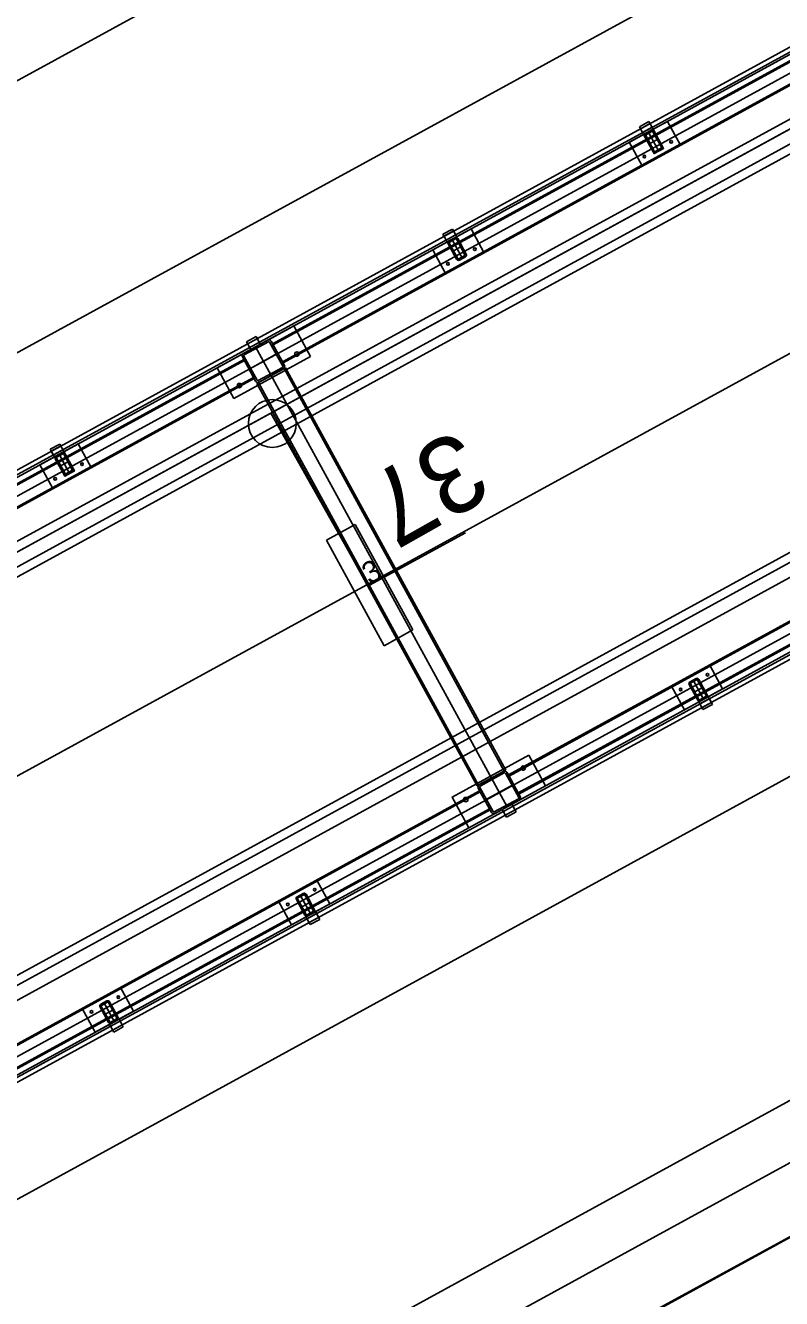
# Model space of a CAD drawing. Extents: x -783978 to -783565, y -1064821 to -1064596.
# Drawn here: x -783759.75 to -783756.29, y -1064681.64 to -1064675.81 of the extents above; entities that cross this region are included whole.
import ezdxf

# ---------------------------------------------------------------- set-up
doc = ezdxf.new("R2010")
doc.units = 0
for name, color, linetype in [('Default', 7, 'Continuous'), ('SO 01_11_01', 7, 'Continuous'), ('SO 01_20_01', 7, 'Continuous'), ('SO 01_50_01', 7, 'Continuous'), ('SO 01_74_01', 7, 'Continuous'), ('SO 01_86_02', 7, 'Continuous'), ('SO 01_86_03', 7, 'Continuous'), ('SO 01_86_04', 7, 'Continuous')]:
    doc.layers.add(name, color=color, linetype=linetype)

# ---------------------------------------------------------------- blocks, each defined once
blk = doc.blocks.new('POINT_DISPLAY')
at = {"layer": 'Default'}
blk.add_line((0, 0), (0, 0), dxfattribs=at)

msp = doc.modelspace()

# ---------------------------------------------------------------- linework, layer by layer
at = {"layer": 'SO 01_11_01'}
msp.add_line((-783772.8819, -1064683.2217), (-783730.898, -1064660.279), dxfattribs=at)
at = {"layer": 'SO 01_20_01'}
for p, q in [((-783735.0054, -1064663.7532), (-783787.4671, -1064692.4555)), ((-783735.2041, -1064664.4318), (-783786.7885, -1064692.6541)), ((-783786.6445, -1064692.9173), (-783735.3233, -1064664.839)), ((-783738.0171, -1064666.3812), (-783786.4402, -1064692.874)), ((-783786.421, -1064692.9091), (-783737.9979, -1064666.4163)), ((-783737.8741, -1064667.2605), (-783785.3352, -1064693.2269)), ((-783785.6531, -1064694.3127), (-783737.23, -1064667.82)), ((-783737.0912, -1064667.858), (-783785.7805, -1064694.4964)), ((-783737.2108, -1064667.855), (-783785.6339, -1064694.3478)), ((-783785.6366, -1064694.7596), (-783736.9472, -1064668.1212)), ((-783746.2961, -1064673.8055), (-783785.8354, -1064695.4379))]:
    msp.add_line(p, q, dxfattribs=at)
at = {"layer": 'SO 01_50_01'}
for p, q in [((-783786.7885, -1064692.6541), (-783725.4827, -1064659.1131)), ((-783760.47, -1064678.255), (-783756.0835, -1064675.8552)), ((-783760.4699, -1064678.2551), (-783756.0835, -1064675.8552)), ((-783760.4699, -1064678.2551), (-783756.0835, -1064675.8552))]:
    msp.add_line(p, q, dxfattribs=at)
for points in [[(-783784.7751, -1064696.3401), (-783745.2333, -1064674.7064)], [(-783784.6553, -1064696.5595), (-783745.1133, -1064674.9257)]]:
    msp.add_lwpolyline(points, dxfattribs=at)
at = {"layer": 'SO 01_74_01'}
for p, q in [((-783735.2185, -1064664.4055), (-783786.6099, -1064692.5222)), ((-783786.6003, -1064692.5398), (-783735.2089, -1064664.423)), ((-783785.4388, -1064694.6628), (-783745.8293, -1064672.9921)), ((-783745.8197, -1064673.0096), (-783785.4292, -1064694.6803)), ((-783756.054, -1064675.8675), (-783758.62, -1064677.2714)), ((-783756.051, -1064675.873), (-783758.617, -1064677.2769)), ((-783758.5751, -1064677.3536), (-783756.009, -1064675.9497)), ((-783758.572, -1064677.3591), (-783756.006, -1064675.9552)), ((-783756.8967, -1064676.2544), (-783756.9405, -1064676.2784)), ((-783756.9405, -1064676.2784), (-783756.9213, -1064676.3135)), ((-783756.8919, -1064676.2632), (-783756.9357, -1064676.2872)), ((-783756.9357, -1064676.2872), (-783756.9261, -1064676.3048)), ((-783756.9261, -1064676.3048), (-783756.8823, -1064676.2808)), ((-783756.9213, -1064676.3135), (-783756.8775, -1064676.2895)), ((-783756.8775, -1064676.2895), (-783756.8967, -1064676.2544)), ((-783756.8823, -1064676.2808), (-783756.8919, -1064676.2632)), ((-783757.7959, -1064676.7464), (-783757.8398, -1064676.7704)), ((-783757.7911, -1064676.7552), (-783757.835, -1064676.7792)), ((-783757.7767, -1064676.7815), (-783757.7959, -1064676.7464)), ((-783757.7815, -1064676.7727), (-783757.7911, -1064676.7552)), ((-783757.8398, -1064676.7704), (-783757.8206, -1064676.8055)), ((-783757.835, -1064676.7792), (-783757.8254, -1064676.7967)), ((-783757.8254, -1064676.7967), (-783757.7815, -1064676.7727)), ((-783757.8206, -1064676.8055), (-783757.7767, -1064676.7815)), ((-783758.739, -1064677.2624), (-783758.6951, -1064677.2384)), ((-783758.7198, -1064677.2975), (-783758.739, -1064677.2624)), ((-783758.6759, -1064677.2735), (-783758.7198, -1064677.2975)), ((-783758.6951, -1064677.2384), (-783758.6759, -1064677.2735)), ((-783758.62, -1064677.2714), (-783758.572, -1064677.3591)), ((-783758.617, -1064677.2769), (-783758.5751, -1064677.3536)), ((-783758.7516, -1064677.3434), (-783761.3177, -1064678.7473)), ((-783758.7486, -1064677.3489), (-783761.3147, -1064678.7528)), ((-783758.7036, -1064677.4311), (-783758.7516, -1064677.3434)), ((-783758.7067, -1064677.4256), (-783758.7486, -1064677.3489)), ((-783758.6916, -1064677.4531), (-783758.56, -1064677.3811)), ((-783758.6846, -1064677.4492), (-783758.5671, -1064677.3849)), ((-783758.5671, -1064677.3849), (-783757.5591, -1064679.2272)), ((-783758.56, -1064677.3811), (-783757.5521, -1064679.2234)), ((-783761.2727, -1064678.8295), (-783758.7067, -1064677.4256)), ((-783761.2697, -1064678.835), (-783758.7036, -1064677.4311)), ((-783757.6837, -1064679.2954), (-783758.6916, -1064677.4531)), ((-783757.6767, -1064679.2915), (-783758.6846, -1064677.4492)), ((-783759.5943, -1064677.7304), (-783759.6382, -1064677.7544)), ((-783759.6382, -1064677.7544), (-783759.619, -1064677.7894)), ((-783759.5895, -1064677.7391), (-783759.6334, -1064677.7631)), ((-783759.6238, -1064677.7807), (-783759.5799, -1064677.7567)), ((-783759.5751, -1064677.7654), (-783759.5943, -1064677.7304)), ((-783759.5799, -1064677.7567), (-783759.5895, -1064677.7391)), ((-783759.6334, -1064677.7631), (-783759.6238, -1064677.7807)), ((-783759.619, -1064677.7894), (-783759.5751, -1064677.7654)), ((-783754.9741, -1064677.8414), (-783757.5401, -1064679.2453)), ((-783754.971, -1064677.8469), (-783757.5371, -1064679.2508)), ((-783757.4951, -1064679.3275), (-783754.9291, -1064677.9236)), ((-783757.4921, -1064679.333), (-783754.9261, -1064677.9291)), ((-783756.6686, -1064678.911), (-783756.6248, -1064678.887)), ((-783756.6494, -1064678.9461), (-783756.6686, -1064678.911)), ((-783756.6638, -1064678.9198), (-783756.62, -1064678.8958)), ((-783756.6542, -1064678.9373), (-783756.6638, -1064678.9198)), ((-783756.6104, -1064678.9133), (-783756.6542, -1064678.9373)), ((-783756.6056, -1064678.9221), (-783756.6494, -1064678.9461)), ((-783756.6248, -1064678.887), (-783756.6056, -1064678.9221)), ((-783756.62, -1064678.8958), (-783756.6104, -1064678.9133)), ((-783757.5521, -1064679.2234), (-783757.6837, -1064679.2954)), ((-783757.5591, -1064679.2272), (-783757.6767, -1064679.2915)), ((-783757.5401, -1064679.2453), (-783757.4921, -1064679.333)), ((-783757.5371, -1064679.2508), (-783757.4951, -1064679.3275)), ((-783757.6717, -1064679.3173), (-783760.2378, -1064680.7212)), ((-783757.6687, -1064679.3228), (-783760.2347, -1064680.7267)), ((-783757.6237, -1064679.405), (-783757.6717, -1064679.3173)), ((-783757.6267, -1064679.3995), (-783757.6687, -1064679.3228)), ((-783757.524, -1064679.379), (-783757.5678, -1064679.403)), ((-783757.5048, -1064679.414), (-783757.524, -1064679.379)), ((-783760.1928, -1064680.8034), (-783757.6267, -1064679.3995)), ((-783760.1898, -1064680.8089), (-783757.6237, -1064679.405)), ((-783757.5678, -1064679.403), (-783757.5486, -1064679.438)), ((-783757.5486, -1064679.438), (-783757.5048, -1064679.414)), ((-783758.4671, -1064679.8949), (-783758.4232, -1064679.8709)), ((-783758.4479, -1064679.93), (-783758.4671, -1064679.8949)), ((-783758.4623, -1064679.9037), (-783758.4184, -1064679.8797)), ((-783758.4527, -1064679.9212), (-783758.4623, -1064679.9037)), ((-783758.4088, -1064679.8972), (-783758.4527, -1064679.9212)), ((-783758.404, -1064679.906), (-783758.4479, -1064679.93)), ((-783758.4232, -1064679.8709), (-783758.404, -1064679.906)), ((-783758.4184, -1064679.8797), (-783758.4088, -1064679.8972)), ((-783759.3663, -1064680.3869), (-783759.3224, -1064680.3629)), ((-783759.3615, -1064680.3957), (-783759.3176, -1064680.3717)), ((-783759.3224, -1064680.3629), (-783759.3032, -1064680.398)), ((-783759.3176, -1064680.3717), (-783759.308, -1064680.3892)), ((-783759.3471, -1064680.422), (-783759.3663, -1064680.3869)), ((-783759.3519, -1064680.4132), (-783759.3615, -1064680.3957)), ((-783759.308, -1064680.3892), (-783759.3519, -1064680.4132)), ((-783759.3032, -1064680.398), (-783759.3471, -1064680.422))]:
    msp.add_line(p, q, dxfattribs=at)
for points in [[(-783735.1681, -1064664.4976), (-783787.4762, -1064693.1159)], [(-783734.0882, -1064666.4715), (-783786.3963, -1064695.0898)], [(-783756.8858, -1064676.2941), (-783756.913, -1064676.309)], [(-783756.8827, -1064676.2996), (-783756.91, -1064676.3145)], [(-783756.8994, -1064676.3015), (-783756.8514, -1064676.3893)], [(-783756.8395, -1064676.372), (-783756.8785, -1064676.3008)], [(-783756.834, -1064676.369), (-783756.8729, -1064676.2978)], [(-783756.9168, -1064676.3218), (-783756.8779, -1064676.393)], [(-783756.9113, -1064676.3188), (-783756.8723, -1064676.3899)], [(-783756.8535, -1064676.3334), (-783756.8973, -1064676.3574)], [(-783756.8681, -1064676.3912), (-783756.8408, -1064676.3763)], [(-783756.865, -1064676.3967), (-783756.8378, -1064676.3818)], [(-783757.816, -1064676.8138), (-783757.7771, -1064676.8849)], [(-783757.785, -1064676.786), (-783757.8123, -1064676.801)], [(-783757.8105, -1064676.8108), (-783757.7716, -1064676.8819)], [(-783757.782, -1064676.7916), (-783757.8092, -1064676.8065)], [(-783757.7986, -1064676.7935), (-783757.7506, -1064676.8812)], [(-783757.7527, -1064676.8254), (-783757.7966, -1064676.8494)], [(-783757.7388, -1064676.864), (-783757.7777, -1064676.7928)], [(-783757.7332, -1064676.8609), (-783757.7722, -1064676.7898)], [(-783757.7673, -1064676.8832), (-783757.74, -1064676.8682)], [(-783757.7643, -1064676.8887), (-783757.737, -1064676.8738)], [(-783758.7531, -1064677.3157), (-783758.6426, -1064677.2552)], [(-783758.7493, -1064677.3227), (-783758.6387, -1064677.2623)], [(-783758.6978, -1064677.2855), (-783757.5459, -1064679.391)], [(-783758.6978, -1064677.2855), (-783758.6258, -1064677.4171)], [(-783758.6333, -1064677.2638), (-783758.5728, -1064677.3744)], [(-783758.6263, -1064677.26), (-783758.5658, -1064677.3705)], [(-783758.6974, -1064677.4425), (-783758.7579, -1064677.332)], [(-783758.6904, -1064677.4387), (-783758.7509, -1064677.3282)], [(-783758.596, -1064677.3153), (-783758.7276, -1064677.3873)], [(-783758.5744, -1064677.3798), (-783758.685, -1064677.4403)], [(-783758.5706, -1064677.3868), (-783758.6811, -1064677.4473)], [(-783759.6145, -1064677.7977), (-783759.5755, -1064677.8689)], [(-783759.5834, -1064677.77), (-783759.6107, -1064677.7849)], [(-783759.6089, -1064677.7947), (-783759.57, -1064677.8659)], [(-783759.5804, -1064677.7755), (-783759.6077, -1064677.7904)], [(-783759.5971, -1064677.7774), (-783759.5491, -1064677.8652)], [(-783759.5511, -1064677.8093), (-783759.595, -1064677.8333)], [(-783759.5372, -1064677.8479), (-783759.5761, -1064677.7768)], [(-783759.5317, -1064677.8449), (-783759.5706, -1064677.7737)], [(-783759.5657, -1064677.8671), (-783759.5384, -1064677.8522)], [(-783759.5627, -1064677.8726), (-783759.5354, -1064677.8577)], [(-783756.681, -1064678.8038), (-783756.7083, -1064678.8187)], [(-783756.7121, -1064678.8315), (-783756.6732, -1064678.9027)], [(-783756.7066, -1064678.8285), (-783756.6676, -1064678.8997)], [(-783756.678, -1064678.8093), (-783756.7053, -1064678.8242)], [(-783756.6947, -1064678.8113), (-783756.6467, -1064678.899)], [(-783756.6488, -1064678.8431), (-783756.6926, -1064678.8671)], [(-783756.6348, -1064678.8817), (-783756.6737, -1064678.8106)], [(-783756.6293, -1064678.8787), (-783756.6682, -1064678.8075)], [(-783756.6634, -1064678.9009), (-783756.6361, -1064678.886)], [(-783756.6603, -1064678.9064), (-783756.633, -1064678.8915)], [(-783757.6732, -1064679.2896), (-783757.5626, -1064679.2291)], [(-783757.6693, -1064679.2966), (-783757.5588, -1064679.2361)], [(-783757.6179, -1064679.2594), (-783757.5459, -1064679.391)], [(-783757.5534, -1064679.2377), (-783757.4929, -1064679.3483)], [(-783757.5463, -1064679.2339), (-783757.4859, -1064679.3444)], [(-783757.6175, -1064679.4164), (-783757.6779, -1064679.3059)], [(-783757.6104, -1064679.4126), (-783757.6709, -1064679.302)], [(-783757.5161, -1064679.2892), (-783757.6477, -1064679.3612)], [(-783757.4945, -1064679.3537), (-783757.605, -1064679.4142)], [(-783757.4906, -1064679.3607), (-783757.6012, -1064679.4212)], [(-783758.4795, -1064679.7877), (-783758.5068, -1064679.8027)], [(-783758.4765, -1064679.7933), (-783758.5037, -1064679.8082)], [(-783758.4931, -1064679.7952), (-783758.4451, -1064679.8829)], [(-783758.4333, -1064679.8657), (-783758.4722, -1064679.7945)], [(-783758.4277, -1064679.8626), (-783758.4667, -1064679.7915)], [(-783758.5105, -1064679.8155), (-783758.4716, -1064679.8866)], [(-783758.505, -1064679.8125), (-783758.4661, -1064679.8836)], [(-783758.4472, -1064679.8271), (-783758.4911, -1064679.8511)], [(-783758.4618, -1064679.8849), (-783758.4345, -1064679.8699)], [(-783758.4588, -1064679.8904), (-783758.4315, -1064679.8755)], [(-783759.4097, -1064680.3075), (-783759.3708, -1064680.3786)], [(-783759.3787, -1064680.2797), (-783759.406, -1064680.2946)], [(-783759.4042, -1064680.3044), (-783759.3653, -1064680.3756)], [(-783759.3757, -1064680.2852), (-783759.403, -1064680.3002)], [(-783759.3923, -1064680.2872), (-783759.3443, -1064680.3749)], [(-783759.3464, -1064680.319), (-783759.3903, -1064680.343)], [(-783759.3325, -1064680.3576), (-783759.3714, -1064680.2865)], [(-783759.3269, -1064680.3546), (-783759.3659, -1064680.2835)], [(-783759.361, -1064680.3768), (-783759.3337, -1064680.3619)], [(-783759.358, -1064680.3824), (-783759.3307, -1064680.3674)]]:
    msp.add_lwpolyline(points, dxfattribs=at)
for points in [[(-783756.8117, -1064676.2535), (-783756.9871, -1064676.3495), (-783756.9295, -1064676.4548), (-783756.7541, -1064676.3588)], [(-783756.8775, -1064676.2895), (-783756.9213, -1064676.3135), (-783756.8733, -1064676.4013), (-783756.8295, -1064676.3773)], [(-783757.7109, -1064676.7455), (-783757.8863, -1064676.8415), (-783757.8288, -1064676.9468), (-783757.6533, -1064676.8508)], [(-783758.4456, -1064677.3298), (-783758.7965, -1064677.5218), (-783758.8733, -1064677.3815), (-783758.5224, -1064677.1895)], [(-783759.5093, -1064677.7294), (-783759.6848, -1064677.8254), (-783759.6272, -1064677.9307), (-783759.4517, -1064677.8347)], [(-783759.5751, -1064677.7654), (-783759.619, -1064677.7894), (-783759.571, -1064677.8772), (-783759.5271, -1064677.8532)], [(-783756.559, -1064678.851), (-783756.7344, -1064678.947), (-783756.792, -1064678.8417), (-783756.6166, -1064678.7457)], [(-783757.4472, -1064679.1546), (-783757.7982, -1064679.3466), (-783757.7214, -1064679.4869), (-783757.3705, -1064679.295)], [(-783758.3574, -1064679.8349), (-783758.5329, -1064679.9309), (-783758.5904, -1064679.8256), (-783758.415, -1064679.7297)], [(-783759.2566, -1064680.3269), (-783759.4321, -1064680.4229), (-783759.4897, -1064680.3176), (-783759.3142, -1064680.2216)]]:
    msp.add_lwpolyline(points, close=True, dxfattribs=at)
for centre, radius in [((-783756.7948, -1064676.3469), 0.006), ((-783756.9176, -1064676.4141), 0.006), ((-783757.694, -1064676.8389), 0.006), ((-783757.8168, -1064676.9061), 0.006), ((-783758.5086, -1064677.3188), 0.01), ((-783758.7718, -1064677.4627), 0.01), ((-783759.4924, -1064677.8228), 0.006), ((-783759.6153, -1064677.89), 0.006), ((-783756.6285, -1064678.7864), 0.006), ((-783756.7513, -1064678.8536), 0.006), ((-783757.4719, -1064679.2137), 0.01), ((-783757.7351, -1064679.3577), 0.01), ((-783758.4269, -1064679.7704), 0.006), ((-783758.5497, -1064679.8376), 0.006), ((-783759.3261, -1064680.2623), 0.006), ((-783759.4489, -1064680.3295), 0.006)]:
    msp.add_circle(centre, radius, dxfattribs=at)
for centre, radius, start, end in [((-783756.8812, -1064676.3024), 0.00945, 28.68349, 118.68349), ((-783756.8812, -1064676.3024), 0.00315, 28.68349, 118.68349), ((-783756.9085, -1064676.3173), 0.00945, 118.68349, 208.68349), ((-783756.9085, -1064676.3173), 0.00315, 118.68349, 208.68349), ((-783756.8696, -1064676.3884), 0.00945, 208.68349, 298.68349), ((-783756.8696, -1064676.3884), 0.00315, 208.68349, 298.68349), ((-783756.8423, -1064676.3735), 0.00315, 298.68349, 28.68349), ((-783756.8423, -1064676.3735), 0.00945, 298.68349, 28.68349), ((-783757.8077, -1064676.8093), 0.00945, 118.68349, 208.68349), ((-783757.8077, -1064676.8093), 0.00315, 118.68349, 208.68349), ((-783757.7804, -1064676.7943), 0.00945, 28.68349, 118.68349), ((-783757.7804, -1064676.7943), 0.00315, 28.68349, 118.68349), ((-783757.7688, -1064676.8804), 0.00315, 208.68349, 298.68349), ((-783757.7415, -1064676.8655), 0.00315, 298.68349, 28.68349), ((-783757.7415, -1064676.8655), 0.00945, 298.68349, 28.68349), ((-783757.7688, -1064676.8804), 0.00945, 208.68349, 298.68349), ((-783758.6368, -1064677.2658), 0.012, 28.68349, 118.68349), ((-783758.6368, -1064677.2658), 0.004, 28.68349, 118.68349), ((-783758.7473, -1064677.3262), 0.012, 118.68349, 208.68349), ((-783758.7473, -1064677.3262), 0.004, 118.68349, 208.68349), ((-783758.5763, -1064677.3763), 0.004, 298.68349, 28.68349), ((-783758.5763, -1064677.3763), 0.012, 298.68349, 28.68349), ((-783758.6869, -1064677.4368), 0.012, 208.68349, 298.68349), ((-783758.6869, -1064677.4368), 0.004, 208.68349, 298.68349), ((-783759.6062, -1064677.7932), 0.00945, 118.68349, 208.68349), ((-783759.6062, -1064677.7932), 0.00315, 118.68349, 208.68349), ((-783759.5789, -1064677.7783), 0.00945, 28.68349, 118.68349), ((-783759.5789, -1064677.7783), 0.00315, 28.68349, 118.68349), ((-783759.5672, -1064677.8643), 0.00945, 208.68349, 298.68349), ((-783759.5672, -1064677.8643), 0.00315, 208.68349, 298.68349), ((-783759.54, -1064677.8494), 0.00315, 298.68349, 28.68349), ((-783759.54, -1064677.8494), 0.00945, 298.68349, 28.68349), ((-783756.6765, -1064678.8121), 0.00945, 28.68349, 118.68349), ((-783756.7038, -1064678.827), 0.00945, 118.68349, 208.68349), ((-783756.7038, -1064678.827), 0.00315, 118.68349, 208.68349), ((-783756.6765, -1064678.8121), 0.00315, 28.68349, 118.68349), ((-783756.6649, -1064678.8982), 0.00945, 208.68349, 298.68349), ((-783756.6649, -1064678.8982), 0.00315, 208.68349, 298.68349), ((-783756.6376, -1064678.8832), 0.00315, 298.68349, 28.68349), ((-783756.6376, -1064678.8832), 0.00945, 298.68349, 28.68349), ((-783757.5569, -1064679.2397), 0.012, 28.68349, 118.68349), ((-783757.5569, -1064679.2397), 0.004, 28.68349, 118.68349), ((-783757.6674, -1064679.3001), 0.012, 118.68349, 208.68349), ((-783757.6674, -1064679.3001), 0.004, 118.68349, 208.68349), ((-783757.4964, -1064679.3502), 0.004, 298.68349, 28.68349), ((-783757.4964, -1064679.3502), 0.012, 298.68349, 28.68349), ((-783757.6069, -1064679.4107), 0.012, 208.68349, 298.68349), ((-783757.6069, -1064679.4107), 0.004, 208.68349, 298.68349), ((-783758.4749, -1064679.796), 0.00945, 28.68349, 118.68349), ((-783758.4749, -1064679.796), 0.00315, 28.68349, 118.68349), ((-783758.5022, -1064679.811), 0.00945, 118.68349, 208.68349), ((-783758.5022, -1064679.811), 0.00315, 118.68349, 208.68349), ((-783758.4633, -1064679.8821), 0.00945, 208.68349, 298.68349), ((-783758.4633, -1064679.8821), 0.00315, 208.68349, 298.68349), ((-783758.436, -1064679.8672), 0.00315, 298.68349, 28.68349), ((-783758.436, -1064679.8672), 0.00945, 298.68349, 28.68349), ((-783759.4014, -1064680.3029), 0.00945, 118.68349, 208.68349), ((-783759.4014, -1064680.3029), 0.00315, 118.68349, 208.68349), ((-783759.3742, -1064680.288), 0.00945, 28.68349, 118.68349), ((-783759.3742, -1064680.288), 0.00315, 28.68349, 118.68349), ((-783759.3625, -1064680.3741), 0.00945, 208.68349, 298.68349), ((-783759.3625, -1064680.3741), 0.00315, 208.68349, 298.68349), ((-783759.3352, -1064680.3591), 0.00315, 298.68349, 28.68349), ((-783759.3352, -1064680.3591), 0.00945, 298.68349, 28.68349)]:
    msp.add_arc(centre, radius, start, end, dxfattribs=at)
at = {"layer": 'SO 01_86_02'}
msp.add_lwpolyline([(-783878.1861, -1064744.2753), (-783875.1286, -1064744.3451), (-783874.6948, -1064744.3279), (-783873.2511, -1064744.1567), (-783872.3143, -1064743.9824), (-783871.2185, -1064743.7022), (-783870.5149, -1064743.4863), (-783869.7975, -1064743.2125), (-783869.1775, -1064742.9745), (-783868.7111, -1064742.7654), (-783868.3945, -1064742.6073), (-783868.078, -1064742.4492), (-783860.9748, -1064738.5687), (-783850.6715, -1064732.6113), (-783846.2461, -1064730.1894), (-783839.9469, -1064727.0857), (-783822.4265, -1064717.4271), (-783813.3562, -1064712.518), (-783804.2851, -1064707.6104), (-783794.4737, -1064702.2521), (-783784.6611, -1064696.8962), (-783775.7336, -1064692.0133), (-783766.8056, -1064687.1312), (-783750.6261, -1064678.2817)], dxfattribs=at)
at = {"layer": 'SO 01_86_03'}
msp.add_lwpolyline([(-783747.0305, -1064676.621), (-783747.6236, -1064677.108), (-783750.7299, -1064678.7824), (-783751.6662, -1064678.8522), (-783782.6812, -1064695.8307), (-783782.8877, -1064696.6917), (-783783.0615, -1064696.8198), (-783783.3595, -1064696.8031), (-783786.8168, -1064690.1799), (-783787.333, -1064689.2371), (-783735.2095, -1064660.6967), (-783724.8208, -1064663.0486), (-783722.5212, -1064661.7932)], dxfattribs=at)
at = {"layer": 'SO 01_86_04'}
for p, q in [((-783758.6285, -1064677.5895), (-783758.1683, -1064678.4042)), ((-783758.2416, -1064678.0989), (-783758.3732, -1064678.1709)), ((-783758.2416, -1064678.0989), (-783758.3732, -1064678.1709)), ((-783758.3732, -1064678.1709), (-783758.2416, -1064678.0989)), ((-783758.3732, -1064678.1709), (-783758.2416, -1064678.0989)), ((-783757.9776, -1064678.5814), (-783758.2416, -1064678.0989)), ((-783757.9776, -1064678.5814), (-783758.2416, -1064678.0989)), ((-783758.2416, -1064678.0989), (-783757.9776, -1064678.5814)), ((-783758.2416, -1064678.0989), (-783757.9776, -1064678.5814)), ((-783758.1754, -1064678.3762), (-783757.7368, -1064678.1362)), ((-783758.3732, -1064678.1709), (-783758.1092, -1064678.6534)), ((-783758.3732, -1064678.1709), (-783758.1092, -1064678.6534)), ((-783758.1092, -1064678.6534), (-783758.3732, -1064678.1709)), ((-783758.1092, -1064678.6534), (-783758.3732, -1064678.1709)), ((-783758.1092, -1064678.6534), (-783757.9776, -1064678.5814)), ((-783758.1092, -1064678.6534), (-783757.9776, -1064678.5814)), ((-783757.9776, -1064678.5814), (-783758.1092, -1064678.6534)), ((-783757.9776, -1064678.5814), (-783758.1092, -1064678.6534))]:
    msp.add_line(p, q, dxfattribs=at)
for points in [[(-783738.3222, -1064666.4797), (-783740.5325, -1064667.689), (-783743.1715, -1064669.1328), (-783745.7538, -1064670.5456), (-783748.4385, -1064672.0145), (-783751.0413, -1064673.4385), (-783753.6847, -1064674.8847), (-783756.3281, -1064676.3309), (-783758.9715, -1064677.7772), (-783761.6149, -1064679.2234), (-783764.2583, -1064680.6696), (-783766.9018, -1064682.1159), (-783769.4633, -1064683.5173), (-783772.109, -1064684.9648), (-783774.7882, -1064686.4306), (-783778.1382, -1064688.2722), (-783783.8139, -1064691.3971), (-783785.747, -1064692.4898)], [(-783747.063, -1064670.9765), (-783746.9575, -1064671.1681), (-783786.6893, -1064692.8619), (-783786.185, -1064693.7636)]]:
    msp.add_lwpolyline(points, dxfattribs=at)
msp.add_circle((-783758.621, -1064677.6365), 0.1097, dxfattribs=at)

# ---------------------------------------------------------------- block references
at = {"layer": 'SO 01_86_04', "xscale": 0.010000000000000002, "yscale": 0.009999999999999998, "rotation": 28.683491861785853}
for p in [(-783758.2416, -1064678.0989), (-783758.2416, -1064678.0989), (-783758.3732, -1064678.1709), (-783758.3732, -1064678.1709), (-783757.9776, -1064678.5814), (-783757.9776, -1064678.5814), (-783758.1092, -1064678.6534), (-783758.1092, -1064678.6534)]:
    msp.add_blockref('POINT_DISPLAY', p, dxfattribs=at)

# ---------------------------------------------------------------- texts
at = {"layer": 'SO 01_86_04'}
for s, height, rotation, p in [('37', 0.351, 209.46001, (-783757.7702, -1064677.6546)), ('3', 0.1, 28.68349, (-783758.1754, -1064678.3762))]:
    msp.add_text(s, height=height, rotation=rotation, dxfattribs=at).set_placement(p)

doc.saveas('drawing.dxf')
